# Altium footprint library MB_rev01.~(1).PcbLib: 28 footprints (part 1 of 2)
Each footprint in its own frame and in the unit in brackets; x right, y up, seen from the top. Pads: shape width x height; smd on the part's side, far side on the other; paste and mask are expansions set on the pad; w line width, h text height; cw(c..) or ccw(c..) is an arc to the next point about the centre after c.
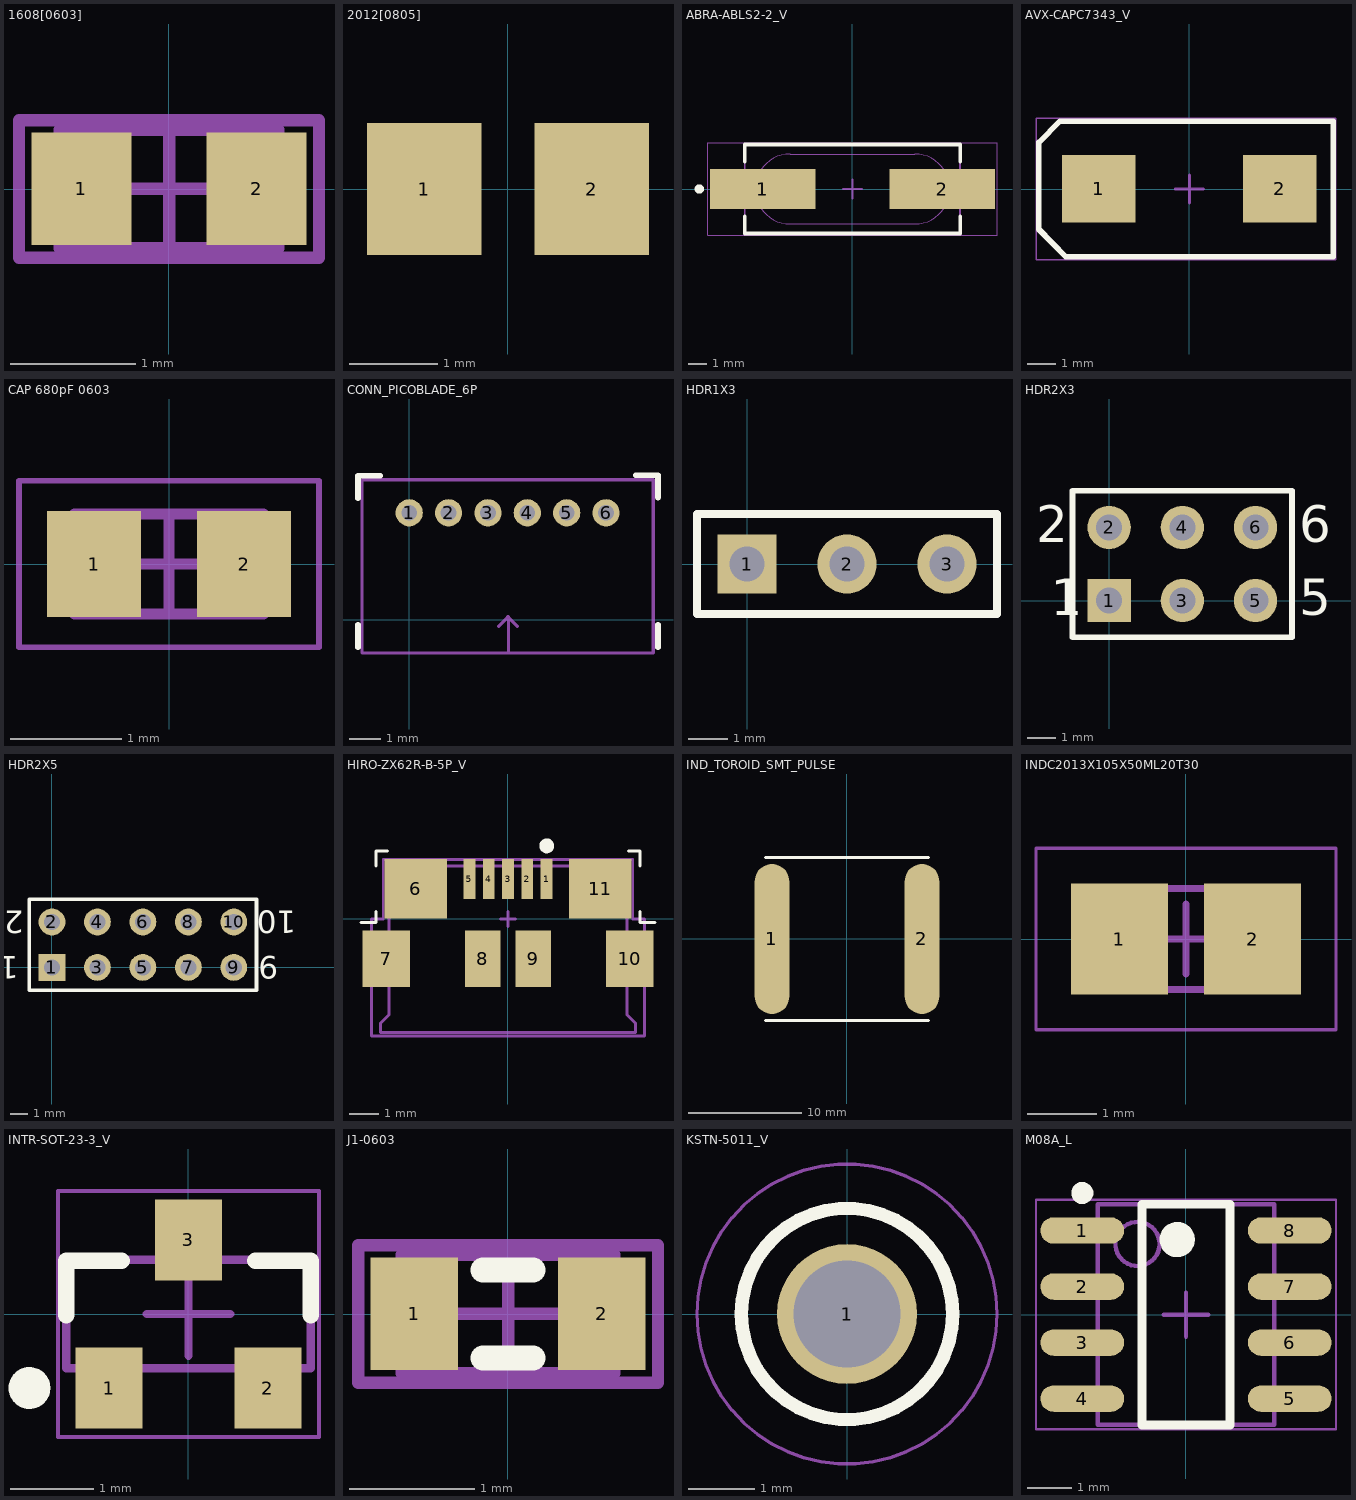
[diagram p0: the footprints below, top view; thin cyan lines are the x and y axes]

## 1608[0603] [mm]
pads (2):
  rect 0.8x0.9 smd: 1(-0.7,0) 2(0.7,0)
Mechanical 13:
  lines w0.1: -0.875,-0.475 -0.875,0.475 0.875,0.475 0.875,-0.475 -0.875,-0.475
Mechanical 15:
  lines w0.1: -0.475,0 0.475,0 ; 0,-0.475 0,0.475 ; -1.2,-0.55 -1.2,0.55 1.2,0.55 1.2,-0.55 -1.2,-0.55
3D body: height 1.3, standoff 0, extent -0.875,-0.475 0.875,0.475

## 2012[0805] [mm]
pads (2):
  rect 1.3x1.5 smd: 1(-0.95,0) 2(0.95,0)

## ABRA-ABLS2-2_V [mm]
pads (2):
  rect 5.6x2.1 smd: 1(-4.75,0) 2(4.75,0)
Top Overlay:
  circle w0.25: c-8.1,0 r0.125
  lines w0.2: -5.7,-1.45 -5.7,-2.35 5.7,-2.35 5.7,-1.45 ; -5.7,1.45 -5.7,2.35 5.7,2.35 5.7,1.45
Mechanical 13:
  lines w0.05: -3.3,-1.85 cw(c-3.3,0) -3.3,1.85 3.3,1.85 cw(c3.3,0) 3.3,-1.85 -3.3,-1.85
  lines w0.1: -5.7,-2.35 5.7,-2.35 5.7,2.35 -5.7,2.35 -5.7,-2.35
Mechanical 15:
  lines w0.05: -7.65,-2.45 -7.65,2.45 7.65,2.45 7.65,-2.45 -7.65,-2.45
  lines w0.1: -0.5,0 0.5,0 ; 0,-0.5 0,0.5
3D body: height 0.5, standoff 0, extent -5.699,-2.349 5.699,2.349
3D body: height 3.3, standoff 0.5, extent -5.151,-1.851 5.151,1.851

## AVX-CAPC7343_V [mm]
pads (2):
  rect 2.6x2.4 smd: 1(-3.202,0.007) 2(3.198,0.007)
Top Overlay:
  lines w0.2: -4.369,-2.4 5.08,-2.4 5.08,2.4 -4.575,2.4 -5.325,1.65 -5.325,-1.425 -4.362,-2.4
Mechanical 15:
  lines w0.05: -5.425,-2.5 5.18,-2.5 5.18,2.5 -5.425,2.5 -5.425,-2.5
  lines w0.1: -0.5,0 0.5,0 ; 0,-0.5 0,0.5
3D body: height 0.3, standoff 0, extent 3.308,-0.855 3.512,0.915
3D body: height 0.3, standoff 0, extent -3.487,-0.869 -3.392,0.82
3D body "TAJD227K010R.step": height 2.9, standoff 0, extent -3.473,-2.032 3.473,2.039

## CAP 680pF 0603 [mm]
pads (2):
  rect 0.85x0.95 smd: 1(-0.675,0) 2(0.675,0)
Mechanical 13:
  lines w0.1: -0.85,-0.45 0.85,-0.45 0.85,0.45 -0.85,0.45 -0.85,-0.45
Mechanical 15:
  lines w0.05: -1.35,-0.75 1.35,-0.75 1.35,0.75 -1.35,0.75 -1.35,-0.75
  lines w0.1: -0.45,0 0.45,0 ; 0,-0.45 0,0.45
3D body: height 0.9, standoff 0, extent 0.55,-0.45 0.85,0.45
3D body: height 0.9, standoff 0, extent -0.85,-0.45 -0.55,0.45
3D body: height 0.9, standoff 0, extent -0.55,-0.45 0.55,0.45

## CONN_PICOBLADE_6P [mm]
pads (6):
  round 0.864 hole 0.5: 1(0,3.4) 2(1.25,3.4) 3(2.5,3.4) 4(3.75,3.4) 5(5,3.4) 6(6.25,3.4)
Top Overlay:
  lines w0.178: -1.626,-0.864 -1.626,-0.152 ; -1.626,3.861 -1.626,4.572 -0.914,4.572 ; 7.188,4.597 7.899,4.597 7.899,3.886 ; 7.899,-0.864 7.899,-0.152
Mechanical 13:
  lines w0.102: 2.845,-0.203 3.15,0.102 3.15,-1.05 ; 3.124,0.102 3.429,-0.203 ; -1.5,-1.05 7.75,-1.05 7.75,4.45 -1.5,4.45 -1.5,-1.05
3D body: height 3.5, standoff 0, extent -1.5,-1.05 7.75,4.45

## HDR1X3 [mm]
pads (3):
  rect 1.5x1.5 hole 0.9: 1(0,0)
  round 1.5 hole 0.9: 2(2.54,0) 3(5.08,0)
Top Overlay:
  lines w0.2: -1.27,-1.27 6.35,-1.27 6.35,1.27 -1.27,1.27 -1.27,-1.27

## HDR2X3 [mm]
pads (6):
  rect 1.5x1.5 hole 0.9: 1(0,0)
  round 1.5 hole 0.9: 2(0,2.54) 3(2.54,0) 4(2.54,2.54) 5(5.08,0) 6(5.08,2.54)
Top Overlay:
  lines w0.2: 1.482,-1.27 6.35,-1.27 ; 6.35,-1.27 -1.27,-1.27 -1.27,3.81 6.35,3.81 6.35,-1.27
  text "1" at -2.032,-0.508 h1.27
  text "2" at -2.54,2.032 h1.27
  text "5" at 6.604,-0.508 h1.27
  text "6" at 6.604,2.032 h1.27

## HDR2X5 [mm]
pads (10):
  rect 1.5x1.5 hole 0.9: 1(0,0)
  round 1.5 hole 0.9: 2(0,2.54) 3(2.54,0) 4(2.54,2.54) 5(5.08,0) 6(5.08,2.54) 7(7.62,0) 8(7.62,2.54) 9(10.16,0) 10(10.16,2.54)
Top Overlay:
  lines w0.2: -1.27,-1.27 -1.27,3.81 11.43,3.81 11.43,-1.27 -1.27,-1.27
  text "2" at -1.589,3.175 h1.27
  text "1" at -1.843,0.635 h1.27
  text "9" at 12.635,0.635 h1.27
  text "10" at 13.651,3.175 h1.27

## HIRO-ZX62R-B-5P_V [mm]
pads (11):
  rect 0.4x1.35 smd: 1(1.3,1.338) 2(0.65,1.338) 3(0,1.338) 4(-0.65,1.338) 5(-1.3,1.338)
  rect 2.1x2 smd: 6(-3.1,1.012) 11(3.1,1.012)
  rect 1.6x1.9 smd: 7(-4.1,-1.338) 10(4.1,-1.338)
  rect 1.2x1.9 smd: 8(-0.85,-1.338) 9(0.85,-1.338)
Top Overlay:
  circle w0.25: c1.304,2.46 r0.125
  lines w0.1: -4.953,-0.127 -4.445,-0.127 -4.445,0.254 ; -4.445,1.778 -4.445,2.286 -4.064,2.286 ; 4.064,2.286 4.445,2.286 4.445,1.778 ; 4.445,0.254 4.445,-0.127 4.953,-0.127
Mechanical 13:
  lines w0.1: -4,1.78 -4,-0.72 -4.572,-0.72 -4.572,-1.778 -4,-1.778 -4,-3.22 -4.3,-3.52 -4.3,-3.82 4.3,-3.82 4.3,-3.52 4,-3.22 4,-1.778 4.572,-1.778 4.572,-0.72 4,-0.72 4,1.78 ; -4,1.78 4,1.78 ; -4,1.78 4,1.78
Mechanical 15:
  lines w0.1: -0.254,0 0.254,0 ; 0,-0.254 0,0.254 ; -4.6,-3.937 -4.6,-2.8 -4.6,0 -4.2,0 -4.2,2 4.2,2 4.2,0 4.6,0 4.6,-2.8 4.6,-3.937 -4.6,-3.937
3D body "ZX62R-B-5P.stp": height 2.71, standoff -0.23, extent -4.4,-3.953 4.4,1.778

## IND_TOROID_SMT_PULSE [mil]
pads (2):
  oval 120x520 smd: 1(-260,0) 2(260,0)
Top Overlay:
  lines w10: -282,-282 282,-282 ; -282,282 282,282
3D body: height 360, standoff 0, extent -285,-284.87 285,284.88

## INDC2013X105X50ML20T30 [mm]
pads (2):
  rect 1.39x1.59 smd: 1(-0.955,0) 2(0.955,0)
Mechanical 13:
  lines w0.1: -1.1,-0.725 1.1,-0.725 1.1,0.725 -1.1,0.725 -1.1,-0.725
Mechanical 15:
  lines w0.05: -2.15,-1.3 2.15,-1.3 2.15,1.3 -2.15,1.3 -2.15,-1.3
  lines w0.1: -0.5,0 0.5,0 ; 0,-0.5 0,0.5
3D body "INDC2013X11M.step": height 1.05, standoff 0, extent -1.1,-0.725 1.1,0.725

## INTR-SOT-23-3_V [mm]
pads (3):
  rect 0.802x0.972 smd: 1(-0.95,-0.885) 2(0.95,-0.885) 3(0,0.885)
Top Overlay:
  circle w0.25: c-1.901,-0.885 r0.125
  lines w0.2: -1.46,-0.014 -1.46,0.621 ; -1.46,0.635 -0.801,0.635 ; 0.801,0.635 1.46,0.635 ; 1.46,-0.014 1.46,0.621
Mechanical 13:
  lines w0.1: -1.46,-0.65 -1.46,0.65 1.46,0.65 1.46,-0.65 -1.46,-0.65
Mechanical 15:
  lines w0.05: -1.56,-1.471 -1.56,1.471 1.56,1.471 1.56,-1.471 -1.56,-1.471
  lines w0.1: -0.5,0 0.5,0 ; 0,-0.5 0,0.5
3D body: height 1.12, standoff 0.01, extent -1.46,-0.65 1.46,0.65

## J1-0603 [mm]
pads (2):
  rect 0.7x0.9 smd: 1(-0.75,0) 2(0.75,0)
Top Overlay:
  lines w0.2: -0.2,-0.35 0.2,-0.35 ; -0.2,0.35 0.2,0.35
Mechanical 13:
  lines w0.1: -0.85,-0.475 -0.85,0.475 0.85,0.475 0.85,-0.475 -0.85,-0.475
Mechanical 15:
  lines w0.1: -0.475,0 0.475,0 ; 0,-0.475 0,0.475 ; -1.2,-0.55 -1.2,0.55 1.2,0.55 1.2,-0.55 -1.2,-0.55
3D body: height 0.9, standoff 0, extent -0.85,-0.475 0.85,0.475

## KSTN-5011_V [mm]
pads (1):
  round 2.1 hole 1.6: 1(0,0)
Top Overlay:
  circle w0.2: c0,0 r1.585
Mechanical 13:
  circle w0.1: c0,0 r1.585
Mechanical 15:
  circle w0.05: c0,0 r2.25
  lines w0.1: -0.5,0 0.5,0 ; 0,-0.5 0,0.5
3D body "keystone-PN5011.STEP": height 8.13, standoff -3.17, extent -1.587,-1.587 1.588,1.588

## M08A_L [mm]
pads (8):
  oval 1.9x0.6 smd: 1(-2.35,1.905) 2(-2.35,0.635) 3(-2.35,-0.635) 4(-2.35,-1.905) 5(2.35,-1.905) 6(2.35,-0.635) 7(2.35,0.635) 8(2.35,1.905)
Top Overlay:
  circle w0.4: c-0.2,1.7 r0.2
  circle w0.25: c-2.35,2.755 r0.125
  lines w0.2: -1,-2.5 1,-2.5 1,2.5 -1,2.5 -1,-2.5
Mechanical 13:
  circle w0.1: c-1.1,1.6 r0.5
  lines w0.1: -2,-2.5 2,-2.5 2,2.5 -2,2.5 -2,-2.5
Mechanical 15:
  lines w0.05: -3.4,-2.6 3.4,-2.6 3.4,2.6 -3.4,2.6 -3.4,-2.6
  lines w0.1: -0.5,0 0.5,0 ; 0,-0.5 0,0.5
3D body: height 1.75, standoff 0.1, extent -2,-2.5 2,2.5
